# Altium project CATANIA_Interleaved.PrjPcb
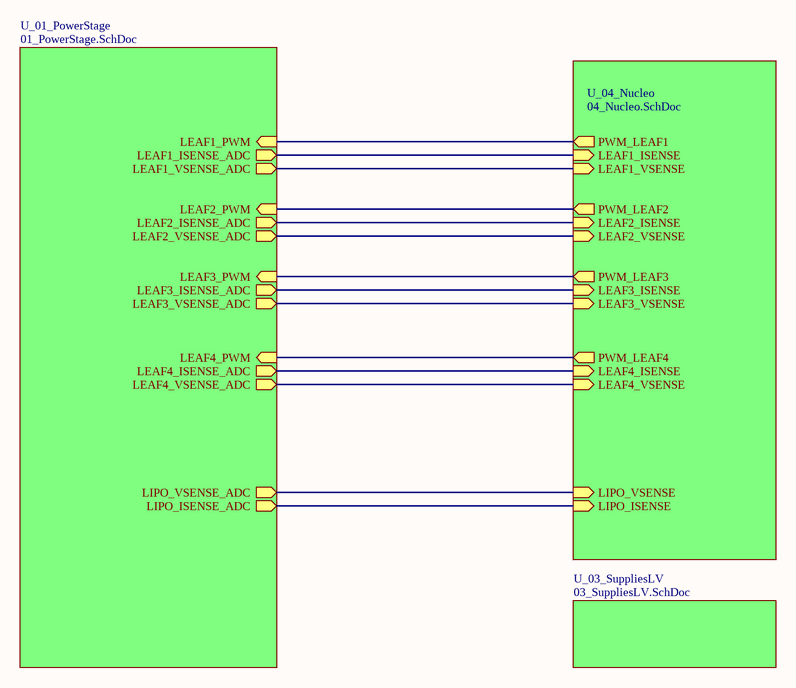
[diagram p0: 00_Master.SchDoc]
5 sheets, 298 parts. Net scope: hierarchical (ports join the sheet entries above them; power ports are global).
Board file: PCB1.PcbDoc
Sheets:
  00_Master.SchDoc
    U_01_PowerStage = 01_PowerStage.SchDoc
      U_01_Leaf = 02_Leaf.SchDoc
      U_02_Leaf = 02_Leaf.SchDoc
      U_03_Leaf = 02_Leaf.SchDoc
      U_04_Leaf = 02_Leaf.SchDoc
    U_04_Nucleo = 04_Nucleo.SchDoc
    U_03_SuppliesLV = 03_SuppliesLV.SchDoc

## Sheet 00_Master.SchDoc
size A4; SheetNumber: 1; SheetTotal: 5

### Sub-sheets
U_01_PowerStage = 01_PowerStage.SchDoc: LIPO_VSENSE_ADC (out), LEAF4_VSENSE_ADC (out), LEAF4_ISENSE_ADC (out), LEAF3_VSENSE_ADC (out), LEAF3_ISENSE_ADC (out), LEAF3_PWM (in), LEAF4_PWM (in), LEAF2_VSENSE_ADC (out), LEAF2_ISENSE_ADC (out), LEAF2_PWM (in), LEAF1_VSENSE_ADC (out), LEAF1_ISENSE_ADC (out), LEAF1_PWM (in), LIPO_ISENSE_ADC (out)
U_03_SuppliesLV = 03_SuppliesLV.SchDoc: no entries
U_04_Nucleo = 04_Nucleo.SchDoc: PWM_LEAF1 (out), LEAF1_ISENSE (in), LEAF1_VSENSE (in), PWM_LEAF4 (out), PWM_LEAF2 (out), LEAF2_ISENSE (in), LEAF3_VSENSE (in), LEAF3_ISENSE (in), LEAF2_VSENSE (in), PWM_LEAF3 (out), LIPO_ISENSE (in), LIPO_VSENSE (in), LEAF4_VSENSE (in), LEAF4_ISENSE (in)

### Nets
NetC10_1: sheet U_01_PowerStage/LIPO_VSENSE_ADC, sheet U_04_Nucleo/LIPO_VSENSE
NetC13_1: sheet U_01_PowerStage/LIPO_ISENSE_ADC, sheet U_04_Nucleo/LIPO_ISENSE
NetC27_1_1: sheet U_01_PowerStage/LEAF1_ISENSE_ADC, sheet U_04_Nucleo/LEAF1_ISENSE
NetC27_2_1: sheet U_01_PowerStage/LEAF2_ISENSE_ADC, sheet U_04_Nucleo/LEAF2_ISENSE
NetC27_3_1: sheet U_01_PowerStage/LEAF3_ISENSE_ADC, sheet U_04_Nucleo/LEAF3_ISENSE
NetC27_4_1: sheet U_01_PowerStage/LEAF4_ISENSE_ADC, sheet U_04_Nucleo/LEAF4_ISENSE
NetC29_1_1: sheet U_01_PowerStage/LEAF1_VSENSE_ADC, sheet U_04_Nucleo/LEAF1_VSENSE
NetC29_2_1: sheet U_01_PowerStage/LEAF2_VSENSE_ADC, sheet U_04_Nucleo/LEAF2_VSENSE
NetC29_3_1: sheet U_01_PowerStage/LEAF3_VSENSE_ADC, sheet U_04_Nucleo/LEAF3_VSENSE
NetC29_4_1: sheet U_01_PowerStage/LEAF4_VSENSE_ADC, sheet U_04_Nucleo/LEAF4_VSENSE
NetR13_1_2: sheet U_01_PowerStage/LEAF1_PWM, sheet U_04_Nucleo/PWM_LEAF1
NetR13_2_2: sheet U_01_PowerStage/LEAF2_PWM, sheet U_04_Nucleo/PWM_LEAF2
NetR13_3_2: sheet U_01_PowerStage/LEAF3_PWM, sheet U_04_Nucleo/PWM_LEAF3
NetR13_4_2: sheet U_01_PowerStage/LEAF4_PWM, sheet U_04_Nucleo/PWM_LEAF4

## Sheet 01_PowerStage.SchDoc
size A4; SheetNumber: 2; SheetTotal: 5; SPICEModelCacheNELIVHSU: <root> / <DocumentId>NELIVHSU</DocumentId> / </root>
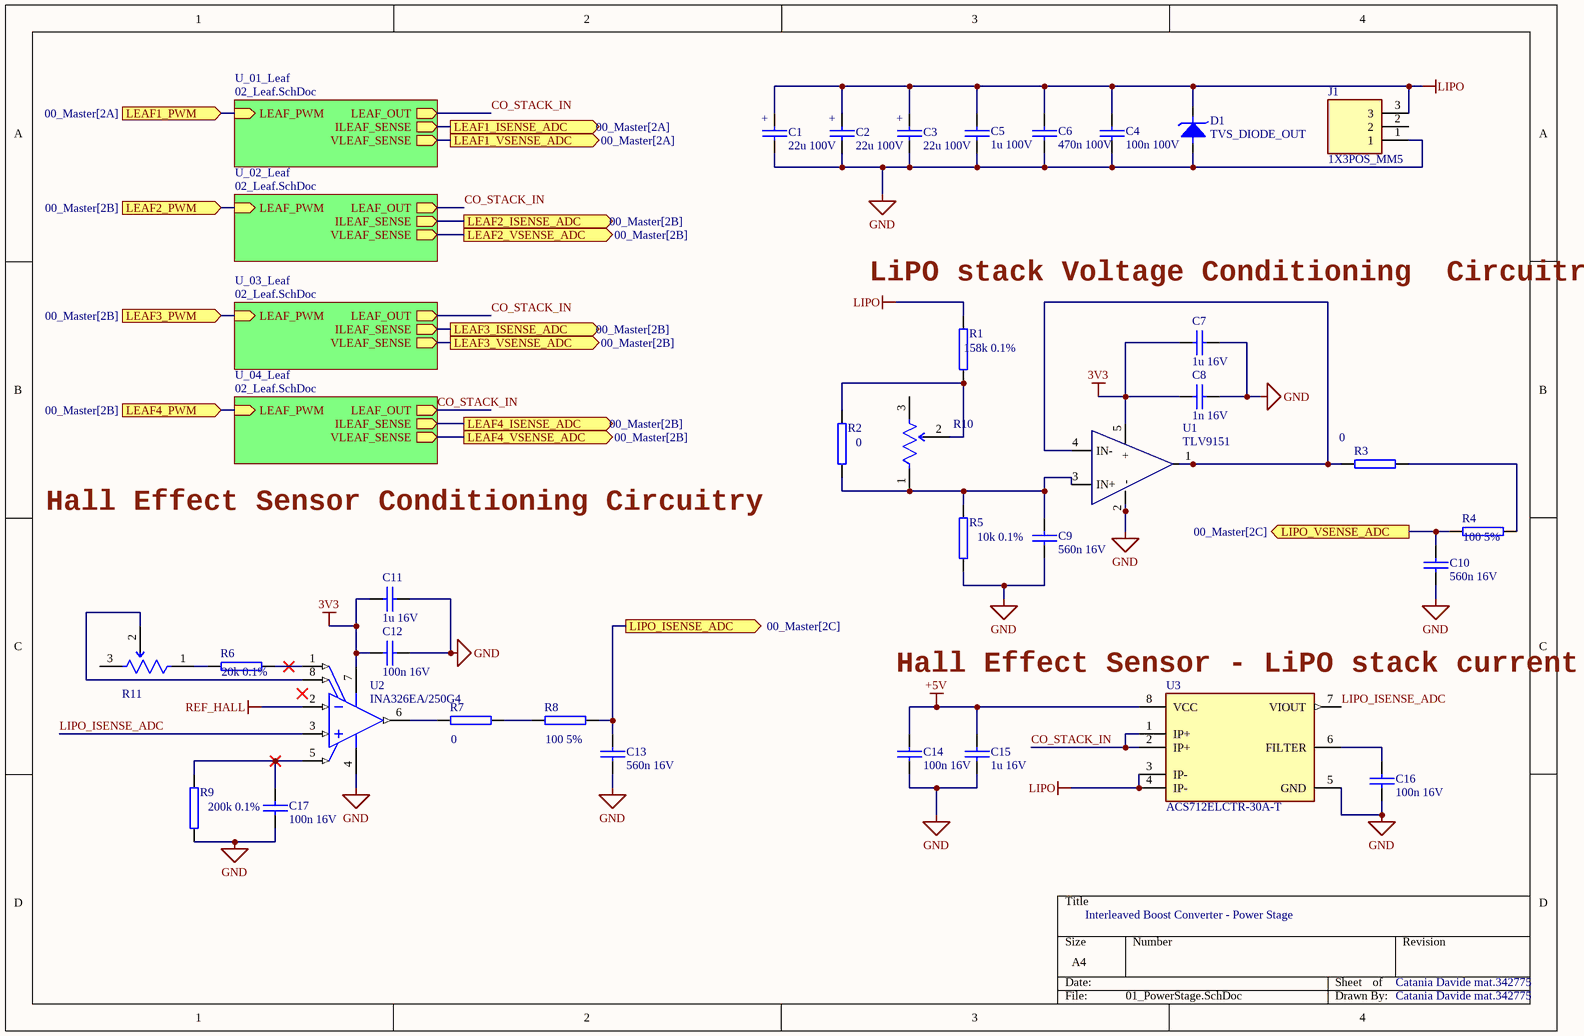
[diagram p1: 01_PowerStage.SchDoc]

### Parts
C1  value 22u 100V  [C8X10EL]  (hidden comment: C8X10EL)
C2  value 22u 100V  [C8X10EL]  (hidden comment: C8X10EL)
C3  value 22u 100V  [C8X10EL]  (hidden comment: C8X10EL)
C4  value 100n 100V  [C0805]  (hidden comment: C0805)
C5  value 1u 100V  [C0805]  (hidden comment: C0805)
C6  value 470n 100V  [C0805]  (hidden comment: C0805)
C7  value 1u 16V  [C0805]  (hidden comment: C0805)
C8  value 1n 16V  [C0805]  (hidden comment: C0805)
C9  value 560n 16V  [C0805]  (hidden comment: C0805)
C10  value 560n 16V  [C0805]  (hidden comment: C0805)
C11  value 1u 16V  [C0805]  (hidden comment: C0805)
C12  value 100n 16V  [C0805]  (hidden comment: C0805)
C13  value 560n 16V  [C0805]  (hidden comment: C0805)
C14  value 100n 16V  [C0805]  (hidden comment: C0805)
C15  value 1u 16V  [C0805]  (hidden comment: C0805)
C16  value 100n 16V  [C0805]  (hidden comment: C0805)
C17  value 100n 16V  [C0805]  (hidden comment: C0805)
D1  TVS_DIODE_OUT  [DO214AA]
J1  1X3POS_MM5  [1X3POS_MM5]
R1  value 158k 0.1%  [R0805]  (hidden comment: R0805)
R2  value 0  [R0805]  (hidden comment: R0805)
R3  value 0  [R0805]  (hidden comment: R0805)
R4  value 100 5%  [R0805]  (hidden comment: R0805)
R5  value 10k 0.1%  [R0805]  (hidden comment: R0805)
R6  value 20k 0.1%  [R0805]  (hidden comment: R0805)
R7  value 0  [R0805]  (hidden comment: R0805)
R8  value 100 5%  [R0805]  (hidden comment: R0805)
R9  value 200k 0.1%  [R0805]  (hidden comment: R0805)
R10  3361  [TRIM-3361P-MFG]  (value not drawn)
R11  3361  [TRIM-3361P-MFG]  (value not drawn)
U1  TLV9151  [SOT23-5]
U2  INA326EA/250G4  [TI-DGK8_L]
U3  ACS712ELCTR-30A-T  [SOIC8_MFG_56MM]

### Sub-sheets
U_01_Leaf = 02_Leaf.SchDoc: LEAF_PWM (in), VLEAF_SENSE (out), LEAF_OUT (out), ILEAF_SENSE (out)
U_02_Leaf = 02_Leaf.SchDoc: LEAF_OUT (out), LEAF_PWM (in), ILEAF_SENSE (out), VLEAF_SENSE (out)
U_03_Leaf = 02_Leaf.SchDoc: LEAF_OUT (out), LEAF_PWM (in), ILEAF_SENSE (out), VLEAF_SENSE (out)
U_04_Leaf = 02_Leaf.SchDoc: LEAF_OUT (out), LEAF_PWM (in), ILEAF_SENSE (out), VLEAF_SENSE (out)

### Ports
LEAF1_ISENSE_ADC (out, see 00_Master[2A]), LEAF1_PWM (in, see 00_Master[2A]), LEAF1_VSENSE_ADC (out, see 00_Master[2A]), LEAF2_ISENSE_ADC (out, see 00_Master[2B]), LEAF2_PWM (in, see 00_Master[2B]), LEAF2_VSENSE_ADC (out, see 00_Master[2B]), LEAF3_ISENSE_ADC (out, see 00_Master[2B]), LEAF3_PWM (in, see 00_Master[2B]), LEAF3_VSENSE_ADC (out, see 00_Master[2B]), LEAF4_ISENSE_ADC (out, see 00_Master[2B]), LEAF4_PWM (in, see 00_Master[2B]), LEAF4_VSENSE_ADC (out, see 00_Master[2B]), LIPO_ISENSE_ADC (out, see 00_Master[2C]), LIPO_VSENSE_ADC (out, see 00_Master[2C])

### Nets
3V3: C7.1 C8.1 C11.1 C12.1 U1.5(+) U2.7(V+)
+5V: C14.1 C15.1 U3.8(VCC)
GND: C1.2 C2.2 C3.2 C4.2 C5.2 C6.2 C7.2 C8.2 C9.2 C10.2 C11.2 C12.2 C13.2 C14.2 C15.2 C16.2 C17.2 D1.A J1.1 R5.1 R9.2 U1.2(-) U2.4(V-) U3.5(GND)
LIPO: C1.1 C2.1 C3.1 C4.1 C5.1 C6.1 D1.K J1.3 R1.2 U3.3(IP-) U3.4(IP-)
REF_HALL: U2.2(VIN-)
CO_STACK_IN: U3.1(IP+) U3.2(IP+) ; sheet U_01_Leaf/LEAF_OUT, sheet U_02_Leaf/LEAF_OUT, sheet U_03_Leaf/LEAF_OUT, sheet U_04_Leaf/LEAF_OUT
LIPO_ISENSE_ADC: U2.3(VIN+) U3.7(VIOUT)
NetC9_1: C9.1 R2.1 R5.2 R10.1(CCW) U1.3(IN+)
NetC10_1: C10.1 R4.2 ; port LIPO_VSENSE_ADC
NetC13_1: C13.1 R8.1 ; port LIPO_ISENSE_ADC
NetC16_1: C16.1 U3.6(FILTER)
NetC17_1: C17.1 R9.1 U2.5(R2)
NetC27_1_1: port LEAF1_ISENSE_ADC, sheet U_01_Leaf/ILEAF_SENSE
NetC27_2_1: port LEAF2_ISENSE_ADC, sheet U_02_Leaf/ILEAF_SENSE
NetC27_3_1: port LEAF3_ISENSE_ADC, sheet U_03_Leaf/ILEAF_SENSE
NetC27_4_1: port LEAF4_ISENSE_ADC, sheet U_04_Leaf/ILEAF_SENSE
NetC29_1_1: port LEAF1_VSENSE_ADC, sheet U_01_Leaf/VLEAF_SENSE
NetC29_2_1: port LEAF2_VSENSE_ADC, sheet U_02_Leaf/VLEAF_SENSE
NetC29_3_1: port LEAF3_VSENSE_ADC, sheet U_03_Leaf/VLEAF_SENSE
NetC29_4_1: port LEAF4_VSENSE_ADC, sheet U_04_Leaf/VLEAF_SENSE
NetR1_1: R1.1 R2.2 R10.2(WIPER)
NetR3_1: R3.1 R4.1
NetR3_2: R3.2 U1.1(OUT) U1.4(IN-)
NetR6_1: R6.1 R11.1(CCW)
NetR6_2: R6.2 U2.1(R1)
NetR7_1: R7.1 R8.2
NetR7_2: R7.2 U2.6(VO)
NetR11_2: R11.2(WIPER) U2.8(R1)
NetR13_1_2: port LEAF1_PWM, sheet U_01_Leaf/LEAF_PWM
NetR13_2_2: port LEAF2_PWM, sheet U_02_Leaf/LEAF_PWM
NetR13_3_2: port LEAF3_PWM, sheet U_03_Leaf/LEAF_PWM
NetR13_4_2: port LEAF4_PWM, sheet U_04_Leaf/LEAF_PWM

Not connected (* = marked no-connect by the designer): J1 2; R10 3(CW); R11 3(CW)

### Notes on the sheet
- LiPO stack Voltage Conditioning  Circuitry
- Hall Effect Sensor Conditioning Circuitry
- (near U3) Hall Effect Sensor - LiPO stack current
- Interleaved Boost Converter - Power Stage
- Catania Davide mat.342775

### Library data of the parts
C1-C3 = C8X10EL: 22uF 100V 121mA@120Hz ±20% SMD, D8xL10mm Aluminum Electrolytic Capacitors - SMD ROHS; Manufacturer: KYOCERA AVX; Manufacturer Part Number: UUX2A220MNL6GS; Dissipation Factor: 8%; Leakage Current: 66µA; Life (Hours): 2000hours; Polarity: Polar; Ripple Current: 121mA
C4-C17 = C0805: C0G Ceramic Smd Ceramic Capacitor
D1 = TVS_DIODE: DIODO SMB
J1 = 1X3POS_MM5: Connector; Manufacturer_Name: Phoenix Contact; Manufacturer_Part_Number: 1935174
R1-R9 = R0805: SMD 0805 RESISTOR
R10 R11 = TRIMPOT_3361_14INCH: Trimmer, Cermet, 0.5W, 100000ohm, 300V, 10% +/-Tol, 100ppm/Cel, 1 Turn(s), 2826; NexarPartId: 1034199; Manufacturer: Bourns; Manufacturer Part Number: 3361P-1-503GLF; Power Rating: 500mW; Temperature Coefficient: 100ppm/°C; Number of Turns: 1; Value: 100k
U1 = TLV9151_SOT23-5: Operational Amplifier, 1 Func, 750uV Offset-Max; Manufacturer: Texas Instruments; Manufacturer Part Number: TLV9151IDBVR
U2 = INA326EA/250: Precision, Low Drift, CMOS Instrumentation Amplifier 8-VSSOP -40 to 85; Manufacturer: Texas Instruments; Manufacturer Lifecycle Status: ACTIVE; CMRR(Min)(dB): 100; SubFamily: Single Supply; Vs(Min)(V): 2.7; Input Bias Current (+/-)(Max)(nA): 2; Gain(V/V): Less than 0.1 to Greater than 1000; Non-Linearity (+/-)(Max)(%): 0.01; Number of Channels: 1; Input Offset Drift (+/-)(Max)(uV/Degrees Celsius): 0.4; Eco-Plan: Green (RoHS & no Sb/Br); Vs(Max)(V): 5.5; Noise at 1kHz(Typ)(nV/rt(Hz)): 33; Quiescent Current (+/-)(Typ)(mA): 2.4; -3db Bandwidth: 1kHz; Common Mode Rejection Ratio: 100dB; Input Bias Current: 2nA; Input Offset Voltage (Vos): 100µV; Max Supply Voltage: 5.5V; Min Supply Voltage: 2.7V; Nominal Supply Current: 3.4mA; Operating Supply Current: 2.4mA; Output Current per Channel: 25mA; Power Supply Rejection Ratio (PSRR): 93.98dB; Value: 10GΩ; Voltage Gain: 80dB
U3 = ACS712ELCTR-30A-T: 66 5¦Ìs Analog 4.5V 13mA 5.5V Bidirectional ¡À1.5% 30A ¡À1.5% SOIC-8 SMD mount£¬glue mount; Manufacturer: Allegro MicroSystems; Bandwidth: 80kHz; Linearity: 1.5%; Operating Supply Voltage: 5V; Quiescent Current: 10mA; Number of Channels: 1; Response Time: 5us; Sensitivity: 66mV/A; Body Material: Plastic; Max Junction Temperature (Tj): 165°C; Output Voltage: 8V; Sensing Method: Hall Effect

## Sheet 02_Leaf.SchDoc
size A4; SheetNumber: 3; SheetTotal: 5; SPICEModelCacheJSJKGZRH: <root> / <DocumentId>JSJKGZRH</DocumentId> / </root>
Used 4 times, as channels U_01_PowerStage/U_01_Leaf, U_01_PowerStage/U_02_Leaf, U_01_PowerStage/U_03_Leaf, U_01_PowerStage/U_04_Leaf. Parts and nets are listed once, with the designators drawn on the sheet.
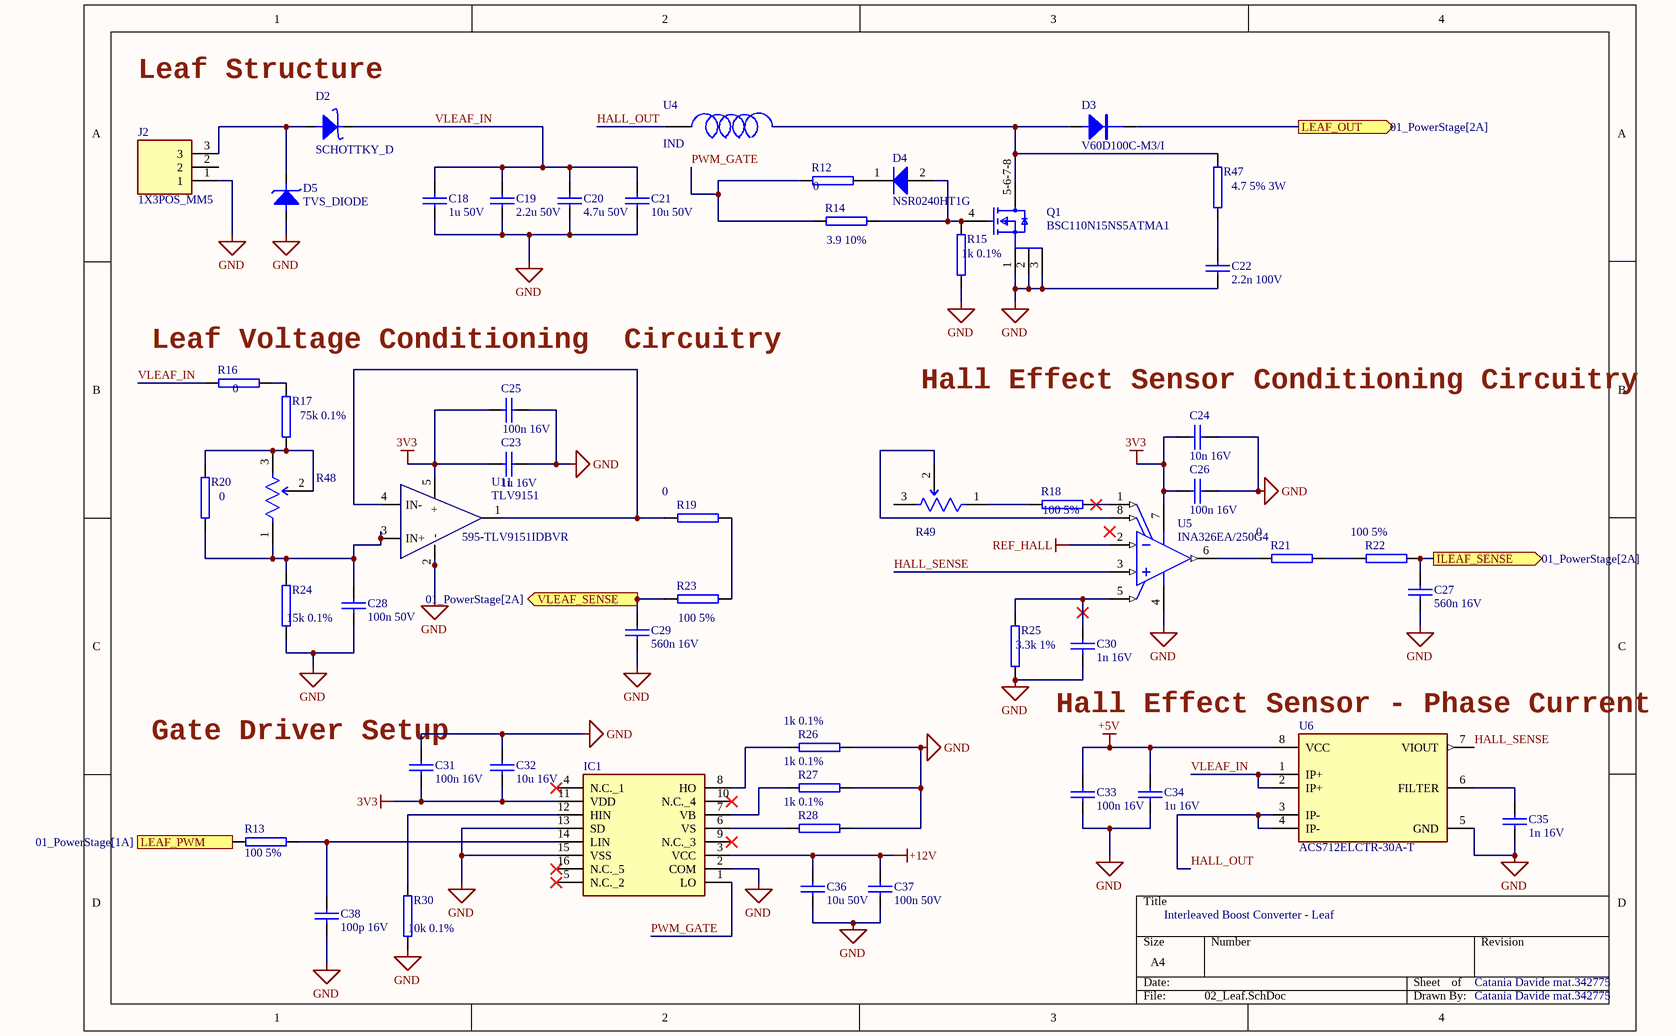
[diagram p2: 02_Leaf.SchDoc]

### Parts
C18  value 1u 50V  [C0805]  (hidden comment: C0805)
C19  value 2.2u 50V  [C0805]  (hidden comment: C0805)
C20  value 4.7u 50V  [C0805]  (hidden comment: C0805)
C21  value 10u 50V  [C0805]  (hidden comment: C0805)
C22  value 2.2n 100V  [C0805]  (hidden comment: C0805)
C23  value 1u 16V  [C0805]  (hidden comment: C0805)
C24  value 10n 16V  [C0805]  (hidden comment: C0805)
C25  value 100n 16V  [C0805]  (hidden comment: C0805)
C26  value 100n 16V  [C0805]  (hidden comment: C0805)
C27  value 560n 16V  [C0805]  (hidden comment: C0805)
C28  value 100n 50V  [C0805]  (hidden comment: C0805)
C29  value 560n 16V  [C0805]  (hidden comment: C0805)
C30  value 1n 16V  [C0805]  (hidden comment: C0805)
C31  value 100n 16V  [C0805]  (hidden comment: C0805)
C32  value 10u 16V  [C0805]  (hidden comment: C0805)
C33  value 100n 16V  [C0805]  (hidden comment: C0805)
C34  value 1u 16V  [C0805]  (hidden comment: C0805)
C35  value 1n 16V  [C0805]  (hidden comment: C0805)
C36  value 10u 50V  [C0805]  (hidden comment: C0805)
C37  value 100n 50V  [C0805]  (hidden comment: C0805)
C38  value 100p 16V  [C0805]  (hidden comment: C0805)
D2  SCHOTTKY_D  [TO-263AB]
D3  V60D100C-M3/I  [TO-263-3]
D4  NSR0240HT1G  [ONSC-SOD-323-2-477-02_V]
D5  TVS_DIODE  [DO214AA]
IC1  (no value)  [SOIC127P1032X265-16N]
J2  1X3POS_MM5  [1X3POS_MM5]
Q1  BSC110N15NS5ATMA1  [FP-PG-TDSON-8-MFG]
R12  value 0  [R0805]  (hidden comment: R0805)
R13  value 100 5%  [R0805]  (hidden comment: R0805)
R14  value 3.9 10%  [R0805]  (hidden comment: R0805)
R15  value 1k 0.1%  [R0805]  (hidden comment: R0805)
R16  value 0  [R0805]  (hidden comment: R0805)
R17  value 75k 0.1%  [R0805]  (hidden comment: R0805)
R18  value 100 5%  [R0805]  (hidden comment: R0805)
R19  value 0  [R0805]  (hidden comment: R0805)
R20  value 0  [R0805]  (hidden comment: R0805)
R21  value 0  [R0805]  (hidden comment: R0805)
R22  value 100 5%  [R0805]  (hidden comment: R0805)
R23  value 100 5%  [R0805]  (hidden comment: R0805)
R24  value 15k 0.1%  [R0805]  (hidden comment: R0805)
R25  value 3.3k 1%  [R0805]  (hidden comment: R0805)
R26  value 1k 0.1%  [R0805]  (hidden comment: R0805)
R27  value 1k 0.1%  [R0805]  (hidden comment: R0805)
R28  value 1k 0.1%  [R0805]  (hidden comment: R0805)
R30  value 10k 0.1%  [R0805]  (hidden comment: R0805)
R47  value 4.7 5% 3W  [R2512]  (hidden comment: R2512)
R48  3361  [TRIM-3361P-MFG]  (value not drawn)
R49  3361  [TRIM-3361P-MFG]  (value not drawn)
U4  IND  [B65812N1012D001]
U5  INA326EA/250G4  [TI-DGK8_L]
U6  ACS712ELCTR-30A-T  [SOIC8_MFG_56MM]
U11  TLV9151  Supplier Part Number 1: 595-TLV9151IDBVR  [SOT23-5]

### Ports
ILEAF_SENSE (out, see 01_PowerStage[2A]), LEAF_OUT (out, see 01_PowerStage[2A]), LEAF_PWM (in, see 01_PowerStage[1A]), VLEAF_SENSE (out, see 01_PowerStage[2A])

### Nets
3V3: C23.1 C24.1 C25.1 C26.1 C31.2 C32.2 IC1.11(VDD) U5.7(V+) U11.5(+)
+5V: C33.1 C34.1 U6.8(VCC)
+12V: C36.1 C37.1 IC1.3(VCC)
GND: C18.2 C19.2 C20.2 C21.2 C22.2 C23.2 C24.2 C25.2 C26.2 C27.2 C28.2 C29.2 C30.2 C31.1 C32.1 C33.2 C34.2 C35.2 C36.2 C37.2 C38.2 D5.A IC1.2(COM) IC1.13(SD) IC1.15(VSS) J2.1 Q1.1(S) Q1.2(S) Q1.3(S) R15.2 R24.1 R25.2 R26.1 R27.1 R28.1 R30.1 U5.4(V-) U6.5(GND) U11.2(-)
REF_HALL: U5.2(VIN-)
HALL_OUT: U4.1,_2,_3,_10,_11,_12 U6.3(IP-) U6.4(IP-)
HALL_SENSE: U5.3(VIN+) U6.7(VIOUT)
ILEAF_SENSE: C27.1 R22.1 ; port ILEAF_SENSE
LEAF_OUT: D3.3 ; port LEAF_OUT
LEAF_PWM: R13.2 ; port LEAF_PWM
PWM_GATE: IC1.1(LO) R12.2 R14.2
VLEAF_IN: C18.1 C19.1 C20.1 C21.1 D2.K R16.2 U6.1(IP+) U6.2(IP+)
VLEAF_SENSE: C29.1 R23.2 ; port VLEAF_SENSE
NetC22_1: C22.1 R47.1
NetC28_1: C28.1 R20.1 R24.2 R48.1(CCW) U11.3(IN+)
NetC30_1: C30.1 R25.1 U5.5(R2)
NetC35_1: C35.1 U6.6(FILTER)
NetC38_1: C38.1 IC1.14(LIN) R13.1
NetD2_A: D2.A D5.K J2.3
NetD3_1,2: D3.1,2 Q1.5-6-7-8(D) R47.2 U4.4,_5,_6,_7,_8,_9
NetD4_1: D4.1(K) R12.1
NetD4_2: D4.2(A) Q1.4(G) R14.1 R15.1
NetIC1_6: IC1.6(VS) R28.2
NetIC1_7: IC1.7(VB) R27.2
NetIC1_8: IC1.8(HO) R26.2
NetIC1_12: IC1.12(HIN) R30.2
NetR16_1: R16.1 R17.2
NetR17_1: R17.1 R20.2 R48.2(WIPER) R48.3(CW)
NetR18_1: R18.1 R49.1(CCW)
NetR18_2: R18.2 U5.1(R1)
NetR19_1: R19.1 R23.1
NetR19_2: R19.2 U11.1(OUT) U11.4(IN-)
NetR21_1: R21.1 R22.2
NetR21_2: R21.2 U5.6(VO)
NetR49_2: R49.2(WIPER) U5.8(R1)

Not connected (* = marked no-connect by the designer): IC1 4(N.C._1)* 5(N.C._2)* 9(N.C._3)* 10(N.C._4)* 16(N.C._5)*; J2 2; R49 3(CW)

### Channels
U_01_PowerStage/U_01_Leaf: designators end in _1; ports ILEAF_SENSE=NetC27_1_1 LEAF_OUT=CO_STACK_IN LEAF_PWM=NetR13_1_2 VLEAF_SENSE=NetC29_1_1
U_01_PowerStage/U_02_Leaf: designators end in _2; ports ILEAF_SENSE=NetC27_2_1 LEAF_OUT=CO_STACK_IN LEAF_PWM=NetR13_2_2 VLEAF_SENSE=NetC29_2_1
U_01_PowerStage/U_03_Leaf: designators end in _3; ports ILEAF_SENSE=NetC27_3_1 LEAF_OUT=CO_STACK_IN LEAF_PWM=NetR13_3_2 VLEAF_SENSE=NetC29_3_1
U_01_PowerStage/U_04_Leaf: designators end in _4; ports ILEAF_SENSE=NetC27_4_1 LEAF_OUT=CO_STACK_IN LEAF_PWM=NetR13_4_2 VLEAF_SENSE=NetC29_4_1

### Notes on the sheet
- (near D2) Leaf Structure
- Leaf Voltage Conditioning  Circuitry
- (near C24) Hall Effect Sensor Conditioning Circuitry
- Hall Effect Sensor - Phase Current
- (near C31) Gate Driver Setup
- Interleaved Boost Converter - Leaf
- Catania Davide mat.342775

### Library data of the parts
C18-C38 = C0805: C0G Ceramic Smd Ceramic Capacitor
D2 = SCHOTTKY_D: Rectifier Diode Schottky 40V 20A 3-Pin(2+Tab) D2PAK T/R; Manufacturer: Diotec; Manufacturer Part Number: SK2040YD2R; Manufacturer Lifecycle Status: ACTIVE
D3 = V60D100C-M3/I: DIODO SMB
D4 = NSR0240HT1G: Schottky Barrier Diode, 2-Pin SOD-323, Pb-Free, Tape and Reel; Manufacturer: On Semiconductor; Configuration: Single; IFSM Max (A): 1
D5 = TVS_DIODE: DIODO SMB
IC1 = IR2110S: 500 V high-side and low-side gate driver IC with shutdown, SOIC 16W, RoHS; Manufacturer_Name: Infineon; Manufacturer Part Number: IR2110STRPBF; Channel Type: Independent; Fall Time: 25ns; Max Output current: 2.5A; Max Output Voltage: 20V; Max Power Dissipation: 1.25W; Max Supply Current: 340µA; Min Output Voltage: 10V; Min Supply Voltage: 3.3V; Nominal Supply Voltage (DC): 15V; Number of Channels: 2; Number of Circuits: 1; Output Voltage: 520V; Propagation Delay: 150ns; Rise Time: 35ns; Turn-Off Delay Time: 94ns; Turn-On Delay Time: 120ns
J2 = 1X3POS_MM5: as J1 on sheet 01_PowerStage
Q1 = BSC110N15NS5ATMA1_1: Mosfet, N-Ch, 150V, 76A, Tdson Rohs Compliant: Yes ¦Infineon Technologies BSC110N15NS5ATMA1; Threshold Vgs Min: 3V; Number Of Channels: 1; Pulse Drain Current: 304A; Depletion Mode: False; Reverse Recovery Charge: 46nC; Max Forward Diode Voltage: 1.2V; Transconductance: 58S; Input Capacitace At Vds: 2080pF @ 75V; Max Junction Temp: +150°C; Turn On Delay Time: 10.3ns; Turn Off Delay Time: 14.5ns; Reverse Recovery Time: 45ns; Drain To Source Resistance: 9mΩ; Rthja Max: 50K/W; Power Dissipation: 125W; Gate Charge At Vgs: 28nC @ 10V; Gate To Source Voltage: 20V; Threshold Vgs Max: 4.6V; Typ Forward Diode Voltage: 0.88V; Input Capacitance: 2.08nF; Max Junction Temperature (Tj): 150°C; On-State Resistance: 11mΩ
R12-R28 R30 = R0805: SMD 0805 RESISTOR
R47 = R2512: SMD 2512 RESISTOR
R48 = TRIMPOT_3361_14INCH: as R10 on sheet 01_PowerStage
R49 = TRIMPOT_3361_14INCH: Trimmer, Cermet, 0.5W, 1000ohm, 300V, 10% +/-Tol, 100ppm/Cel, 1 Turn(s), 2619; NexarPartId: 1034199; Manufacturer: Bourns; Manufacturer Part Number: 3361P-1-503GLF; Power Rating: 500mW; Temperature Coefficient: 100ppm/°C; Number of Turns: 1; Value: 1k
U4 = IND: Power Inductor; Manufacturer_Name: TDK
U5 = INA326EA/250: as U2 on sheet 01_PowerStage
U6 = ACS712ELCTR-30A-T: as U3 on sheet 01_PowerStage
U11 = TLV9151_SOT23-5: as U1 on sheet 01_PowerStage

## Sheet 04_Nucleo.SchDoc
size A4; SheetNumber: 5; SheetTotal: 5
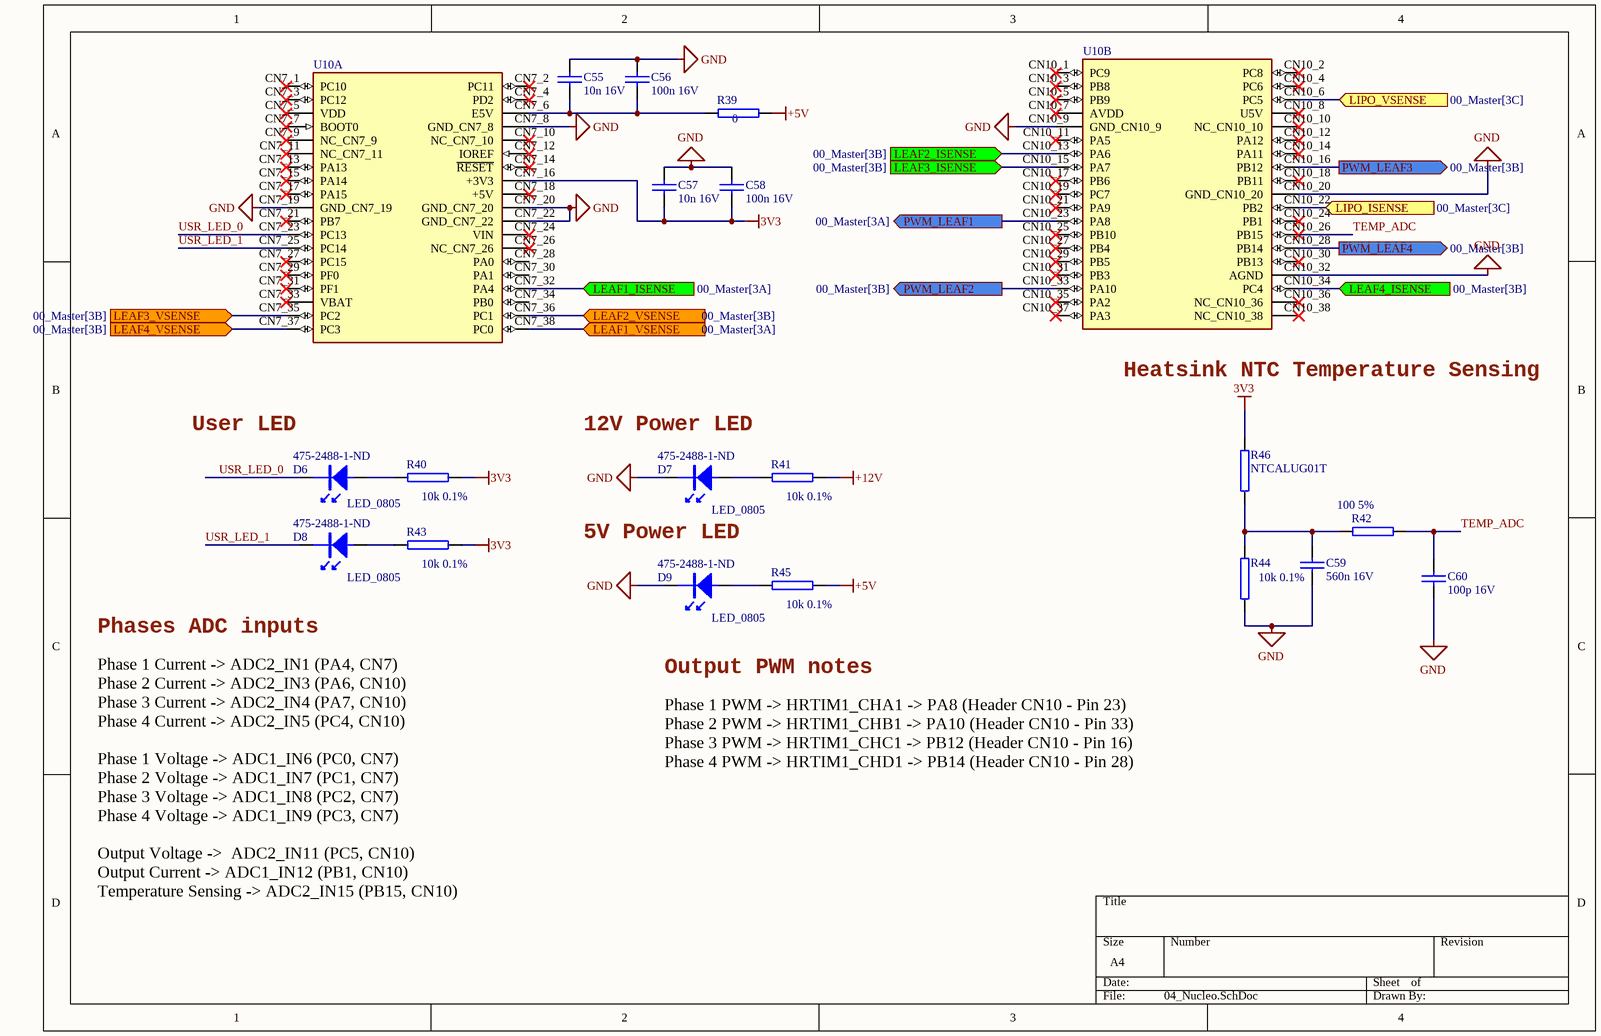
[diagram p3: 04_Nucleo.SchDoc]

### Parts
C55  value 10n 16V  [C0805]  (hidden comment: C0805)
C56  value 100n 16V  [C0805]  (hidden comment: C0805)
C57  value 10n 16V  [C0805]  (hidden comment: C0805)
C58  value 100n 16V  [C0805]  (hidden comment: C0805)
C59  value 560n 16V  [C0805]  (hidden comment: C0805)
C60  value 100p 16V  [C0805]  (hidden comment: C0805)
D6  LED_0805  Supplier Part Number 1: 475-2488-1-ND  [LED_0805]
D7  LED_0805  Supplier Part Number 1: 475-2488-1-ND  [LED_0805]
D8  LED_0805  Supplier Part Number 1: 475-2488-1-ND  [LED_0805]
D9  LED_0805  Supplier Part Number 1: 475-2488-1-ND  [LED_0805]
R39  value 0  [R0805]  (hidden comment: R0805)
R40  value 10k 0.1%  [R0805]  (hidden comment: R0805)
R41  value 10k 0.1%  [R0805]  (hidden comment: R0805)
R42  value 100 5%  [R0805]  (hidden comment: R0805)
R43  value 10k 0.1%  [R0805]  (hidden comment: R0805)
R44  value 10k 0.1%  [R0805]  (hidden comment: R0805)
R45  value 10k 0.1%  [R0805]  (hidden comment: R0805)
R46  NTCALUG01T  [CAP 1.2m TH 4MM]
U10  (no value)  [MODULE_NUCLEO-F072RB]  (parts A,B of 2)

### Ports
LEAF1_ISENSE (in, see 00_Master[3A]), LEAF1_VSENSE (in, see 00_Master[3A]), LEAF2_ISENSE (in, see 00_Master[3B]), LEAF2_VSENSE (in, see 00_Master[3B]), LEAF3_ISENSE (in, see 00_Master[3B]), LEAF3_VSENSE (in, see 00_Master[3B]), LEAF4_ISENSE (in, see 00_Master[3B]), LEAF4_VSENSE (in, see 00_Master[3B]), LIPO_ISENSE (in, see 00_Master[3C]), LIPO_VSENSE (in, see 00_Master[3C]), PWM_LEAF1 (out, see 00_Master[3A]), PWM_LEAF2 (out, see 00_Master[3B]), PWM_LEAF3 (out, see 00_Master[3B]), PWM_LEAF4 (out, see 00_Master[3B])

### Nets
3V3: C57.2 C58.2 R40.1 R43.1 R46.1 U10.CN7_16(+3V3)
+5V: R39.2 R45.1
+12V: R41.1
GND: C55.1 C56.1 C57.1 C58.1 C59.2 C60.2 D7.K D9.K R44.2 U10.CN7_8(GND_CN7_8) U10.CN7_19(GND_CN7_19) U10.CN7_20(GND_CN7_20) U10.CN7_22(GND_CN7_22) U10.CN10_9(GND_CN10_9) U10.CN10_20(GND_CN10_20) U10.CN10_32(AGND)
TEMP_ADC: C60.1 R42.1 U10.CN10_26(PB15)
USR_LED_0: D6.K U10.CN7_23(PC13)
USR_LED_1: D8.K U10.CN7_25(PC14)
NetC10_1: U10.CN10_6(PC5) ; port LIPO_VSENSE
NetC13_1: U10.CN10_22(PB2) ; port LIPO_ISENSE
NetC27_1_1: U10.CN7_32(PA4) ; port LEAF1_ISENSE
NetC27_2_1: U10.CN10_13(PA6) ; port LEAF2_ISENSE
NetC27_3_1: U10.CN10_15(PA7) ; port LEAF3_ISENSE
NetC27_4_1: U10.CN10_34(PC4) ; port LEAF4_ISENSE
NetC29_1_1: U10.CN7_38(PC0) ; port LEAF1_VSENSE
NetC29_2_1: U10.CN7_36(PC1) ; port LEAF2_VSENSE
NetC29_3_1: U10.CN7_35(PC2) ; port LEAF3_VSENSE
NetC29_4_1: U10.CN7_37(PC3) ; port LEAF4_VSENSE
NetC55_2: C55.2 C56.2 R39.1 U10.CN7_6(E5V)
NetC59_1: C59.1 R42.2 R44.1 R46.2
NetD6_A: D6.A R40.2
NetD7_A: D7.A R41.2
NetD8_A: D8.A R43.2
NetD9_A: D9.A R45.2
NetR13_1_2: U10.CN10_23(PA8) ; port PWM_LEAF1
NetR13_2_2: U10.CN10_33(PA10) ; port PWM_LEAF2
NetR13_3_2: U10.CN10_16(PB12) ; port PWM_LEAF3
NetR13_4_2: U10.CN10_28(PB14) ; port PWM_LEAF4

Not connected (* = marked no-connect by the designer): U10 CN7_1(PC10)* CN7_2(PC11)* CN7_3(PC12)* CN7_4(PD2)* CN7_5(VDD)* CN7_7(BOOT0)* CN7_9(NC_CN7_9)* CN7_10(NC_CN7_10)* CN7_11(NC_CN7_11)* CN7_12(IOREF)* CN7_13(PA13)* CN7_14(~{RESET})* CN7_15(PA14)* CN7_17(PA15)* CN7_18(+5V)* CN7_21(PB7)* CN7_24(VIN)* CN7_26(NC_CN7_26)* CN7_27(PC15)* CN7_28(PA0) CN7_29(PF0)* CN7_30(PA1) CN7_31(PF1)* CN7_33(VBAT)* CN7_34(PB0) CN10_1(PC9)* CN10_2(PC8)* CN10_3(PB8)* CN10_4(PC6)* CN10_5(PB9)* CN10_7(AVDD)* CN10_8(U5V)* CN10_10(NC_CN10_10)* CN10_11(PA5)* CN10_12(PA12)* CN10_14(PA11)* CN10_17(PB6)* CN10_18(PB11)* CN10_19(PC7)* CN10_21(PA9)* CN10_24(PB1)* CN10_25(PB10)* CN10_27(PB4)* CN10_29(PB5)* CN10_30(PB13)* CN10_31(PB3)* CN10_35(PA2)* CN10_36(NC_CN10_36)* CN10_37(PA3)* CN10_38(NC_CN10_38)*

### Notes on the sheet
- Heatsink NTC Temperature Sensing
- (near D6) User LED
- 12V Power LED
- 5V Power LED
- Phases ADC inputs
- Output PWM notes
- Phase 1 PWM -> HRTIM1_CHA1 -> PA8 (Header CN10 - Pin 23)
  Phase 2 PWM -> HRTIM1_CHB1 -> PA10 (Header CN10 - Pin 33)
  Phase 3 PWM -> HRTIM1_CHC1 -> PB12 (Header CN10 - Pin 16)
  Phase 4 PWM -> HRTIM1_CHD1 -> PB14 (Header CN10 - Pin 28)
- Phase 1 Current -> ADC2_IN1 (PA4, CN7)
  Phase 2 Current -> ADC2_IN3 (PA6, CN10)
  Phase 3 Current -> ADC2_IN4 (PA7, CN10)
  Phase 4 Current -> ADC2_IN5 (PC4, CN10)
  Phase 1 Voltage -> ADC1_IN6 (PC0, CN7)
  Phase 2 Voltage -> ADC1_IN7 (PC1, CN7)
  Phase 3 Voltage -> ADC1_IN8 (PC2, CN7)
  Phase 4 Voltage -> ADC1_IN9 (PC3, CN7)
  Output Voltage ->  ADC2_IN11 (PC5, CN10)
  Output Current -> ADC1_IN12 (PB1, CN10)
  Temperature Sensing -> ADC2_IN15 (PB15, CN10)

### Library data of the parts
C55-C60 = C0805: C0G Ceramic Smd Ceramic Capacitor
D6-D9 = LED_0805: DIODO LED 20mA 0805; Manufacturer: Osram Opto; Manufacturer Part Number: LOR976-PS-1; Color: Orange; Lens Color: White; Viewing Angle: 160°; Lens Style: Flat,Rectangular,Diffused,Colorless; Forward Current: 25mA; Forward Voltage: 2V; Luminous Intensity: 162.5mcd; Lens Transparency: Diffused; Dominant Wavelength: 606nm; Luminous Flux: 0.735lm; Number of LEDs: 1; Reverse Voltage: 12V; Lens Size: 1.25mm
R39-R45 = R0805: SMD 0805 RESISTOR
R46 = R_FL: Resistor for flying wires
U10 = NUCLEO-F072RB: STM32F072RB, mbed-Enabled Development Nucleo-64 STM32F0 ARMÂ® CortexÂ®-M0 MCU 32-Bit Embedded Evaluation Board; MF: STMicroelectronics

## Sheet 03_SuppliesLV.SchDoc
size A4; SheetNumber: 4; SheetTotal: 5; SPICEModelCacheMDJQDPBO: <root> / <DocumentId>MDJQDPBO</DocumentId> / </root>
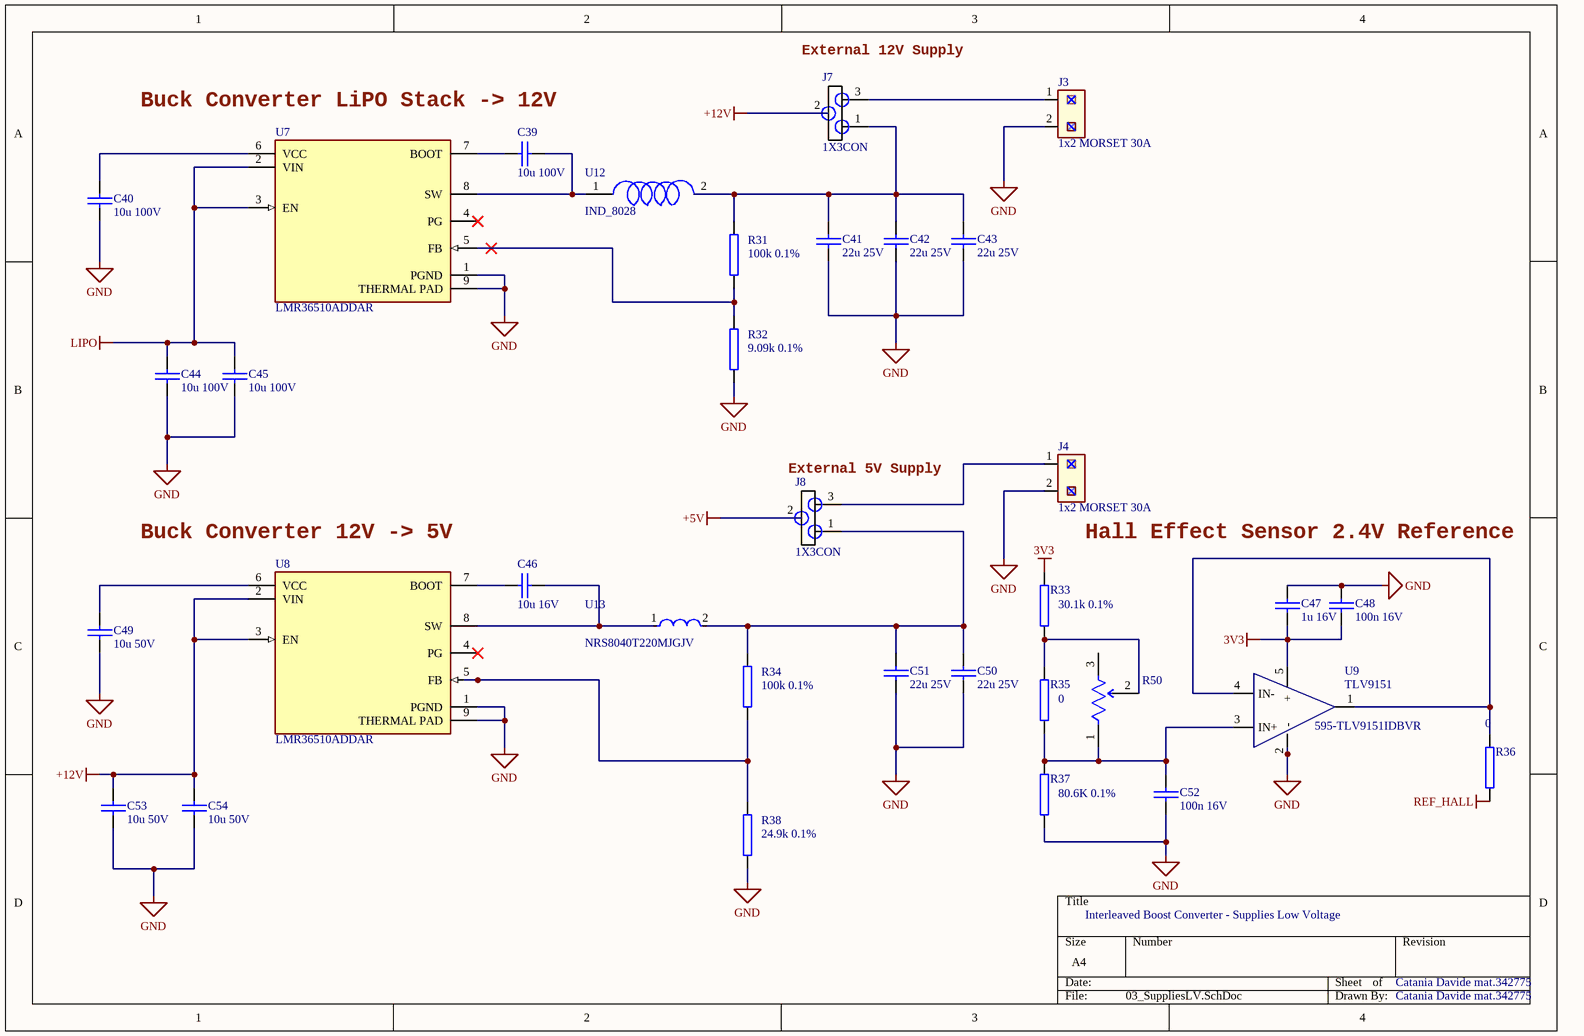
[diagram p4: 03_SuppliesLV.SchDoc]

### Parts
C39  value 10u 100V  [C1210]  (hidden comment: C1210)
C40  value 10u 100V  [C1210]  (hidden comment: C1210)
C41  value 22u 25V  [C1206]  (hidden comment: C1206)
C42  value 22u 25V  [C1206]  (hidden comment: C1206)
C43  value 22u 25V  [C1206]  (hidden comment: C1206)
C44  value 10u 100V  [C1210]  (hidden comment: C1210)
C45  value 10u 100V  [C1210]  (hidden comment: C1210)
C46  value 10u 16V  [C0805]  (hidden comment: C0805)
C47  value 1u 16V  [C0805]  (hidden comment: C0805)
C48  value 100n 16V  [C0805]  (hidden comment: C0805)
C49  value 10u 50V  [C0805]  (hidden comment: C0805)
C50  value 22u 25V  [C1206]  (hidden comment: C1206)
C51  value 22u 25V  [C1206]  (hidden comment: C1206)
C52  value 100n 16V  [C0805]  (hidden comment: C0805)
C53  value 10u 50V  [C0805]  (hidden comment: C0805)
C54  value 10u 50V  [C0805]  (hidden comment: C0805)
J3  1x2 MORSET 30A  [MORSET 1x2 3.5 mm]
J4  1x2 MORSET 30A  [MORSET 1x2 3.5 mm]
J7  1X3CON  [1X3CON_W64P0X254]
J8  1X3CON  [1X3CON_W64P0X254]
R31  value 100k 0.1%  [R0805]  (hidden comment: R0805)
R32  value 9.09k 0.1%  [R0805]  (hidden comment: R0805)
R33  value 30.1k 0.1%  [R0805]  (hidden comment: R0805)
R34  value 100k 0.1%  [R0805]  (hidden comment: R0805)
R35  value 0  [R0805]  (hidden comment: R0805)
R36  value 0  [R0805]  (hidden comment: R0805)
R37  value 80.6K 0.1%  [R0805]  (hidden comment: R0805)
R38  value 24.9k 0.1%  [R0805]  (hidden comment: R0805)
R50  3361  [TRIM-3361P-MFG]  (value not drawn)
U7  LMR36510ADDAR  [HSOIC-8-MFG]
U8  LMR36510ADDAR  [HSOIC-8-MFG]
U9  TLV9151  Supplier Part Number 1: 595-TLV9151IDBVR  [SOT23-5]
U12  IND_8028  [SRU8028]
U13  NRS8040T220MJGJV  [FP-NR8040-H_4_0-MFG]

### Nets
3V3: C47.1 C48.1 R33.2 U9.5(+)
+5V: J8.2
+12V: C53.2 C54.2 J7.2 U8.2(VIN) U8.3(EN)
GND: C40.1 C41.1 C42.1 C43.1 C44.1 C45.1 C47.2 C48.2 C49.1 C50.2 C51.2 C52.1 C53.1 C54.1 J3.2 J4.2 R32.1 R37.1 R38.1 U7.1(PGND) U7.9(THERMAL_PAD) U8.1(PGND) U8.9(THERMAL_PAD) U9.2(-)
LIPO: C44.2 C45.2 U7.2(VIN) U7.3(EN)
REF_HALL: R36.2
NetC39_1: C39.1 U7.7(BOOT)
NetC39_2: C39.2 U7.8(SW) U12.1
NetC40_2: C40.2 U7.6(VCC)
NetC41_2: C41.2 C42.2 C43.2 J7.1 R31.2 U12.2
NetC46_1: C46.1 U8.7(BOOT)
NetC46_2: C46.2 U8.8(SW) U13.1
NetC49_2: C49.2 U8.6(VCC)
NetC50_1: C50.1 C51.1 J8.1 R34.2 U13.2
NetC52_2: C52.2 R35.1 R37.2 R50.1(CCW) U9.3(IN+)
NetJ3_1: J3.1 J7.3
NetJ4_1: J4.1 J8.3
NetR31_1: R31.1 R32.2 U7.5(FB)
NetR33_1: R33.1 R35.2 R50.2(WIPER)
NetR34_1: R34.1 R38.2 U8.5(FB)
NetR36_1: R36.1 U9.1(OUT) U9.4(IN-)

Not connected (* = marked no-connect by the designer): R50 3(CW); U7 4(PG)*; U8 4(PG)*

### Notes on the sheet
- Buck Converter LiPO Stack -> 12V
- (near J7) External 12V Supply
- (near J8) External 5V Supply
- (near U8) Buck Converter 12V -> 5V
- Hall Effect Sensor 2.4V Reference
- Interleaved Boost Converter - Supplies Low Voltage
- Catania Davide mat.342775

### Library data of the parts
C39 C40 C44 C45 = C1210: C0G Ceramic Smd Ceramic Capacitor
C41-C43 C50 C51 = C1206: C0G Ceramic Smd Ceramic Capacitor
C46-C49 C52-C54 = C0805: C0G Ceramic Smd Ceramic Capacitor
J3 J4 = 1x2 MORSET 30A: Manufacturer: CUI Devices; Manufacturer Part Number: TB005-762-02BE
J7 J8 = 1X3CON: Connector; Manufacturer_Name: SAMTEC; Manufacturer_Part_Number: TSW-103-07-G-S-001
R31-R38 = R0805: SMD 0805 RESISTOR
R50 = TRIMPOT_3361_14INCH: as R10 on sheet 01_PowerStage
U7 U8 = LMR36510ADDAR: Switching Regulator, Current-mode, 1A, 460kHz Switching Freq-Max, BICMOS, PDSO8; Manufacturer: Texas Instruments; Manufacturer Lifecycle Status: ACTIVE; Max Duty Cycle: 98%; Max Junction Temperature (Tj): 150°C; Max Supply Voltage: 65V; Min Supply Voltage: 4.2V; Nominal Supply Current: 26µA; Number of Channels: 1; Switching Frequency: 400kHz; Topology: Buck
U9 = TLV9151_SOT23-5: as U1 on sheet 01_PowerStage
U12 = IND_8028: Inductor Power Shielded Wirewound 47uH 30% 100KHz 14Q-Factor Ferrite 1.2A 0.177Ohm DCR 3131 T/R; Manufacturer_Name: TDK; Manufacturer_Part_Number: B65812N1012D001; Manufacturer: Bourns; Manufacturer Part Number: SRU8028-470Y; DC Resistance (DCR): 177mΩ; Value: 47µH; Number of Circuits: 1; Q Factor: 14; Saturation Current: 1A; Self Resonant Frequency: 12MHz
U13 = NRS8040T220MJGJ: Shielded Wirewound Inductor 22uH 20% 2.6A 85.8mΩ SMD Automotive; DC Resistance (DCR): 85.8mR; Test Frequency: 100kHz; Max DC Current: 2.2A; Core Material: Ferrite; Saturation Current: 2.4A; Self Resonant Frequency: 13MHz

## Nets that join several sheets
3V3: 01_PowerStage (6 pins), U_01_PowerStage/U_01_Leaf (9 pins), U_01_PowerStage/U_02_Leaf (9 pins), U_01_PowerStage/U_03_Leaf (9 pins), U_01_PowerStage/U_04_Leaf (9 pins), 04_Nucleo (6 pins), 03_SuppliesLV (C47.1 C48.1 R33.2 U9.5)
+5V: 01_PowerStage (C14.1 C15.1 U3.8), U_01_PowerStage/U_01_Leaf (C33_1.1 C34_1.1 U6_1.8), U_01_PowerStage/U_02_Leaf (C33_2.1 C34_2.1 U6_2.8), U_01_PowerStage/U_03_Leaf (C33_3.1 C34_3.1 U6_3.8), U_01_PowerStage/U_04_Leaf (C33_4.1 C34_4.1 U6_4.8), 04_Nucleo (R39.2 R45.1), 03_SuppliesLV (J8.2)
+12V: U_01_PowerStage/U_01_Leaf (C36_1.1 C37_1.1 IC1_1.3), U_01_PowerStage/U_02_Leaf (C36_2.1 C37_2.1 IC1_2.3), U_01_PowerStage/U_03_Leaf (C36_3.1 C37_3.1 IC1_3.3), U_01_PowerStage/U_04_Leaf (C36_4.1 C37_4.1 IC1_4.3), 04_Nucleo (R41.1), 03_SuppliesLV (5 pins)
GND: 01_PowerStage (24 pins), U_01_PowerStage/U_01_Leaf (39 pins), U_01_PowerStage/U_02_Leaf (39 pins), U_01_PowerStage/U_03_Leaf (39 pins), U_01_PowerStage/U_04_Leaf (39 pins), 04_Nucleo (16 pins), 03_SuppliesLV (24 pins)
LIPO: 01_PowerStage (11 pins), 03_SuppliesLV (C44.2 C45.2 U7.2 U7.3)
REF_HALL: 01_PowerStage (U2.2), U_01_PowerStage/U_01_Leaf (U5_1.2), U_01_PowerStage/U_02_Leaf (U5_2.2), U_01_PowerStage/U_03_Leaf (U5_3.2), U_01_PowerStage/U_04_Leaf (U5_4.2), 03_SuppliesLV (R36.2)
CO_STACK_IN: 01_PowerStage (U3.1 U3.2), U_01_PowerStage/U_01_Leaf (D3_1.3), U_01_PowerStage/U_02_Leaf (D3_2.3), U_01_PowerStage/U_03_Leaf (D3_3.3), U_01_PowerStage/U_04_Leaf (D3_4.3)
NetC10_1: 01_PowerStage (C10.1 R4.2), 04_Nucleo (U10.CN10_6)
NetC13_1: 01_PowerStage (C13.1 R8.1), 04_Nucleo (U10.CN10_22)
NetC27_1_1: U_01_PowerStage/U_01_Leaf (C27_1.1 R22_1.1), 04_Nucleo (U10.CN7_32)
NetC27_2_1: U_01_PowerStage/U_02_Leaf (C27_2.1 R22_2.1), 04_Nucleo (U10.CN10_13)
NetC27_3_1: U_01_PowerStage/U_03_Leaf (C27_3.1 R22_3.1), 04_Nucleo (U10.CN10_15)
NetC27_4_1: U_01_PowerStage/U_04_Leaf (C27_4.1 R22_4.1), 04_Nucleo (U10.CN10_34)
NetC29_1_1: U_01_PowerStage/U_01_Leaf (C29_1.1 R23_1.2), 04_Nucleo (U10.CN7_38)
NetC29_2_1: U_01_PowerStage/U_02_Leaf (C29_2.1 R23_2.2), 04_Nucleo (U10.CN7_36)
NetC29_3_1: U_01_PowerStage/U_03_Leaf (C29_3.1 R23_3.2), 04_Nucleo (U10.CN7_35)
NetC29_4_1: U_01_PowerStage/U_04_Leaf (C29_4.1 R23_4.2), 04_Nucleo (U10.CN7_37)
NetR13_1_2: U_01_PowerStage/U_01_Leaf (R13_1.2), 04_Nucleo (U10.CN10_23)
NetR13_2_2: U_01_PowerStage/U_02_Leaf (R13_2.2), 04_Nucleo (U10.CN10_33)
NetR13_3_2: U_01_PowerStage/U_03_Leaf (R13_3.2), 04_Nucleo (U10.CN10_16)
NetR13_4_2: U_01_PowerStage/U_04_Leaf (R13_4.2), 04_Nucleo (U10.CN10_28)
